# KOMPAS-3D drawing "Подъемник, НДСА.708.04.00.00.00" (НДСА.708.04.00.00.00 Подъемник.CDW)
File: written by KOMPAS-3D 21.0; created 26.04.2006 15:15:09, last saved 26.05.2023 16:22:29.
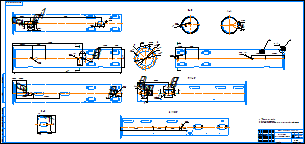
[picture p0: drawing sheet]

Sheet 1: A2x3, landscape

Document properties: Полное имя файла: НДСА.708.04.00.00.00 Подъемник.a3d; Автор: Устинов А.В.; Организация: Эсто-вакуум; Форматы листов документа: A2@4~3; 246268836434: <item xmlns="http://appius.ru/pdm" xmlns:xs="http://www.w3.org/2001/XMLSchema" xmlns:xsi="http://www.w3.org/2001/XMLSchema-instance" xsi:type="item">  <element xmlns:d2p1="http://v8.1c.ru/8.1/data/enterprise/current-config" xsi:type="d2p1:CatalogRef.aps_Элемен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; PLM_CDWXDTO: <item xmlns="http://appius.ru/pdm" xmlns:xs="http://www.w3.org/2001/XMLSchema" xmlns:xsi="http://www.w3.org/2001/XMLSchema-instance" xsi:type="item">  <element xmlns:d2p1="http://v8.1c.ru/8.1/data/enterprise/current-config" xsi:type="d2p1:CatalogRef.aps_Элемен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; Масса: 45.36; 245053002043: <item xmlns="http://appius.ru/pdm" xmlns:xs="http://www.w3.org/2001/XMLSchema" xmlns:xsi="http://www.w3.org/2001/XMLSchema-instance" xsi:type="item">  <element xmlns:d2p1="http://v8.1c.ru/8.1/data/enterprise/current-config" xsi:type="d2p1:CatalogRef.aps_Элемен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; 245053002143: <item xmlns="http://appius.ru/pdm" xmlns:xs="http://www.w3.org/2001/XMLSchema" xmlns:xsi="http://www.w3.org/2001/XMLSchema-instance" xsi:type="item">  <element xmlns:d2p1="http://v8.1c.ru/8.1/data/enterprise/current-config" xsi:type="d2p1:CatalogRef.aps_Элемен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; 245053002243: <item xmlns="http://appius.ru/pdm" xmlns:xs="http://www.w3.org/2001/XMLSchema" xmlns:xsi="http://www.w3.org/2001/XMLSchema-instance" xsi:type="item">  <element xmlns:d2p1="http://v8.1c.ru/8.1/data/enterprise/current-config" xsi:type="d2p1:CatalogRef.aps_Элемен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; PDM_DOCXDTO: <item xmlns="http://appius.ru/pdm" xmlns:xs="http://www.w3.org/2001/XMLSchema" xmlns:xsi="http://www.w3.org/2001/XMLSchema-instance" xsi:type="item">  <element xmlns:d2p1="http://v8.1c.ru/8.1/data/enterprise/current-config" xsi:type="d2p1:CatalogRef.aps_Элемен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; PDM_ITEMXDTO: <item xmlns="http://appius.ru/pdm" xmlns:xs="http://www.w3.org/2001/XMLSchema" xmlns:xsi="http://www.w3.org/2001/XMLSchema-instance" xsi:type="item">  <element xmlns:d2p1="http://v8.1c.ru/8.1/data/enterprise/current-config" xsi:type="d2p1:CatalogRef.aps_Элемен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; PDM_DRAWINGXDTO: <item xmlns="http://appius.ru/pdm" xmlns:xs="http://www.w3.org/2001/XMLSchema" xmlns:xsi="http://www.w3.org/2001/XMLSchema-instance" xsi:type="item">  <element xmlns:d2p1="http://v8.1c.ru/8.1/data/enterprise/current-config" xsi:type="d2p1:CatalogRef.aps_Элемен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

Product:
- Part/product: Подъемник  | designation НДСА.708.04.00.00.00
    Масса: 45.357855
    additional columns: <item xmlns="http://appius.ru/pdm" xmlns:xs="http://www.w3.org/2001/XMLSchema" x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; <item xmlns="http://appius.ru/pdm" xmlns:xs="http://www.w3.org/2001/XMLSchema" x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; <item xmlns="http://appius.ru/pdm" xmlns:xs="http://www.w3.org/2001/XMLSchema" x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; <item xmlns="http://appius.ru/pdm" xmlns:xs="http://www.w3.org/2001/XMLSchema" x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; <item xmlns="http://appius.ru/pdm" xmlns:xs="http://www.w3.org/2001/XMLSchema" x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; <item xmlns="http://appius.ru/pdm" xmlns:xs="http://www.w3.org/2001/XMLSchema" x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
  - Component [detail]: Труба  | designation НДСА.708.04.00.00.01  | pos. 2  | Материал: Труба$d180х10 ГОСТ 8732-78;20 ГОСТ 8731-74$ (density 7859 kg/m3); Масса: 43.448229; additional columns: <item xmlns="http://appius.ru/pdm" xmlns:xs="http://www.w3.org/2001/XMLSchema" x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; <item xmlns="http://appius.ru/pdm" xmlns:xs="http://www.w3.org/2001/XMLSchema" x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; <item xmlns="http://appius.ru/pdm" xmlns:xs="http://www.w3.org/2001/XMLSchema" x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; <item xmlns="http://appius.ru/pdm" xmlns:xs="http://www.w3.org/2001/XMLSchema" x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; <item xmlns="http://appius.ru/pdm" xmlns:xs="http://www.w3.org/2001/XMLSchema" x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; <item xmlns="http://appius.ru/pdm" xmlns:xs="http://www.w3.org/2001/XMLSchema" x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; source file: НДСА.708.04.00.00.01 Труба.CDW, НДСА.708.04.00.00.01 Труба.m3d
  - Component [detail]: Фланец  | designation НДСА.014.01.08.05.01  | pos. 1  | Материал: Сталь 20 ГОСТ 1050-88 (density 7859 kg/m3); Масса: 1.909626; Форматы листов документа: A4; additional columns: <item xmlns="http://appius.ru/pdm" xmlns:xs="http://www.w3.org/2001/XMLSchema" x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; <item xmlns="http://appius.ru/pdm" xmlns:xs="http://www.w3.org/2001/XMLSchema" x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; <item xmlns="http://appius.ru/pdm" xmlns:xs="http://www.w3.org/2001/XMLSchema" x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; <item xmlns="http://appius.ru/pdm" xmlns:xs="http://www.w3.org/2001/XMLSchema" x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; <item xmlns="http://appius.ru/pdm" xmlns:xs="http://www.w3.org/2001/XMLSchema" x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; <item xmlns="http://appius.ru/pdm" xmlns:xs="http://www.w3.org/2001/XMLSchema" x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; source file: НДСА.014.01.08.05.01 Фланец.CDW, НДСА.014.01.08.05.01 Фланец.m3d

Title block, sheet 1: Наименование: Подъемник / Сборочный чертеж; Масса: 45,36; scale: 1:2,5; Количество листов документа: 1; organisation: ЭСТО; Форматы листов документа: A2 3; stored path: D:\WorkPDM\Устинов А.В\adef4302-e6d0-4e78-a7d0-57c469fcab05\УКРД.789.01.05.00.00 СБ Подъемник.cdw; Разработал: Пищагина; Проверил: Белецкий; Утвердил: Виноградов; Разработал, date: 24.05.23

Views: Сверху 16, Сверху, Проекционный вид 17, Местный разрез 1, Проекционный вид 18, Проекционный вид 19, Проекционный вид 20, Вид по стрелке З, Разрез Е-Е, Разрез Ж-Ж, Разрез З-З, Вид по стрелке Д, Вид по стрелке Г, Разрез А-А, Разрез Б-Б, Разрез В-В
Referenced files in C:\Users\s.pischagina\Desktop\PLM\: НДСА.708.04.00.00.00 Подъемник.a3d, НДСА.708.04.00.00.01 Труба.m3d, НДСА.014.01.08.05.01 Фланец.m3d
Referenced files in D:\PLM\: НДСА.014.01.08.05.01 Фланец.m3d
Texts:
  Диаметральный размер
  НДСА.708.04.00.00.00
  Линейный размер
  JS12
  Радиальный размер
  Фланец
  НДСА.014.01.08.05.01
  НДСА.014.01.08.05.01 Фланец
  Труба
  НДСА.708.04.00.00.01
  НДСА.708.04.00.00.01 Труба
  НДСА.708.04.00.00.00 Подъемник
Dimensions and other numbers on the sheet: 160; 208; 232; 22 30'; 11; 8отв; 18±0,215; 14±0,2; 100±0,5; 140±0,3; 200±0,575; -7Н; 8; 4отв; 6,3; 1; 2; 180; 720±0,4; 60±0,2; 50±0,31; 1128; 32; 4; 34±0,31; 107; 3паза; 182±0,575; 270±0,65; 67±0,37; 20±0,2; 2отв; 186±0,23; 728±0,4; 2паза; 28; 68±0,2; 6отв; 250±0,575; 8пазов; 48; 2,5; 76±0,2; 94; 8мест; 6; 177; 341±0,7; 134±0,2; 145±0,5; 1:2,5; 45,36; 24.05.23

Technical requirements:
  3. Сварка по ГОСТ 5264-80
  4.  Покрытие - Эмаль МЛ-152, серая , кроме резьбовых отверстий.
